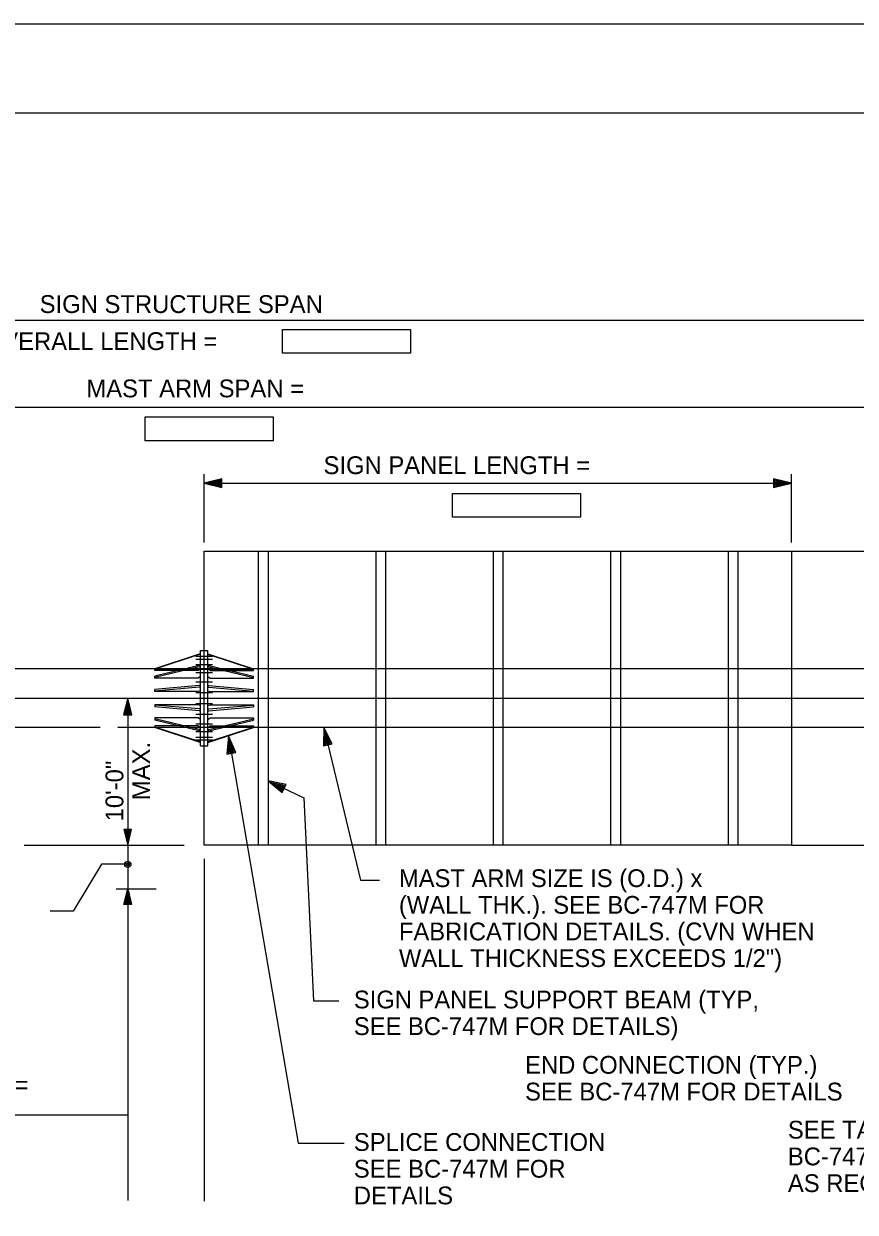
# Model space of a CAD drawing. Extents: x 640117 to 642655, y 297247 to 298435.
# Drawn here: x 641443.9 to 641584, y 298235.3 to 298435.5 of the extents above; entities that cross this region are included whole.
import ezdxf

# ---------------------------------------------------------------- set-up
doc = ezdxf.new("R2010")
doc.units = 0
for name, color, linetype in [('10', 7, 'Continuous'), ('2', 7, 'Continuous'), ('48', 7, 'Continuous'), ('49', 7, 'Continuous'), ('50', 7, 'Continuous'), ('52', 7, 'Continuous'), ('53', 7, 'Continuous'), ('55', 7, 'Continuous'), ('PLT-BNDY', 7, 'Continuous')]:
    doc.layers.add(name, color=color, linetype=linetype)

msp = doc.modelspace()

# ---------------------------------------------------------------- linework, layer by layer
at = {"layer": '10'}
for p, q in [((641461.47, 298321.9), (641461.47, 298237.29)), ((641460.81, 298299.8), (641461.47, 298297.16)), ((641462.13, 298299.8), (641460.81, 298299.8)), ((641461.01, 298299.64), (641461.47, 298297.8)), ((641461.93, 298299.64), (641461.01, 298299.64)), ((641461.21, 298299.49), (641461.47, 298298.45)), ((641461.73, 298299.49), (641461.21, 298299.49)), ((641461.39, 298299.43), (641461.47, 298299.1)), ((641461.47, 298297.16), (641462.13, 298299.8)), ((641461.47, 298297.8), (641461.93, 298299.64)), ((641461.47, 298298.45), (641461.73, 298299.49)), ((641461.47, 298299.1), (641461.55, 298299.41)), ((641444.03, 298297.16), (641470.96, 298297.16)), ((641459.54, 298289.76), (641466.27, 298289.76)), ((641460.81, 298287.12), (641461.47, 298289.76)), ((641461.01, 298287.28), (641461.47, 298289.12)), ((641461.47, 298289.76), (641462.13, 298287.12)), ((641461.47, 298289.12), (641461.93, 298287.28)), ((641462.13, 298287.12), (641460.81, 298287.12)), ((641461.93, 298287.28), (641461.01, 298287.28)), ((641461.21, 298287.43), (641461.47, 298288.47)), ((641461.73, 298287.43), (641461.21, 298287.43)), ((641461.39, 298287.49), (641461.47, 298287.83)), ((641461.47, 298288.47), (641461.73, 298287.43)), ((641461.47, 298287.83), (641461.55, 298287.51)), ((641461.47, 298251.67), (641424.27, 298251.67))]:
    msp.add_line(p, q, dxfattribs=at)
at = {"layer": '2'}
msp.add_line((640998.46, 298420.46), (641784.46, 298420.46), dxfattribs=at)
for points in [[(641487.54, 298383.98), (641509.09, 298383.98), (641509.09, 298379.98), (641487.54, 298379.98)], [(641464.43, 298369.25), (641485.97, 298369.25), (641485.97, 298365.25), (641464.43, 298365.25)], [(641516.19, 298356.38), (641537.74, 298356.38), (641537.74, 298352.38), (641516.19, 298352.38)]]:
    msp.add_lwpolyline(points, close=True, dxfattribs=at)
at = {"layer": '48'}
for p, q in [((641472.96, 298328.95), (641475.73, 298328.95)), ((641472.96, 298328.47), (641475.73, 298328.47)), ((641472.96, 298327.54), (641475.73, 298327.54)), ((641472.96, 298326.23), (641475.73, 298326.23)), ((641472.96, 298324.62), (641475.73, 298324.62)), ((641472.96, 298322.83), (641475.73, 298322.83)), ((641472.96, 298320.97), (641475.73, 298320.97)), ((641472.96, 298319.18), (641475.73, 298319.18)), ((641472.96, 298317.57), (641475.73, 298317.57)), ((641472.96, 298316.25), (641475.73, 298316.25)), ((641472.96, 298315.33), (641475.73, 298315.33)), ((641472.96, 298314.85), (641475.73, 298314.85))]:
    msp.add_line(p, q, dxfattribs=at)
at = {"layer": '49'}
for p, q in [((641474.34, 298346.63), (641573.28, 298346.63)), ((641474.34, 298297.16), (641474.34, 298346.63)), ((641483.47, 298346.63), (641483.47, 298297.16)), ((641485.11, 298346.63), (641485.11, 298297.16)), ((641503.25, 298346.63), (641503.25, 298297.16)), ((641504.9, 298346.63), (641504.9, 298297.16)), ((641523.04, 298346.63), (641523.04, 298297.16)), ((641524.69, 298346.63), (641524.69, 298297.16)), ((641542.83, 298346.63), (641542.83, 298297.16)), ((641544.48, 298346.63), (641544.48, 298297.16)), ((641562.62, 298346.63), (641562.62, 298297.16)), ((641564.27, 298346.63), (641564.27, 298297.16)), ((641573.28, 298346.63), (641573.28, 298297.16)), ((641573.28, 298346.63), (641637.17, 298346.63)), ((641573.28, 298297.16), (641474.34, 298297.16)), ((641573.28, 298297.16), (641637.17, 298297.16))]:
    msp.add_line(p, q, dxfattribs=at)
at = {"layer": '50'}
msp.add_line((641032.47, 298321.9), (641730.35, 298321.9), dxfattribs=at)
at = {"layer": '52'}
for p, q in [((641286.35, 298385.52), (641662.33, 298385.52)), ((641474.34, 298348.13), (641474.34, 298359.59)), ((641477.34, 298358.84), (641474.34, 298358.09)), ((641477.34, 298357.34), (641477.34, 298358.84)), ((641573.28, 298358.09), (641570.28, 298358.84)), ((641570.28, 298358.84), (641570.28, 298357.34)), ((641573.28, 298348.13), (641573.28, 298359.59)), ((641474.34, 298358.09), (641573.28, 298358.09)), ((641474.34, 298358.09), (641477.34, 298357.34)), ((641477.16, 298358.61), (641475.07, 298358.09)), ((641475.07, 298358.09), (641477.16, 298357.57)), ((641476.99, 298358.39), (641475.81, 298358.09)), ((641475.81, 298358.09), (641476.99, 298357.8)), ((641476.92, 298358.18), (641476.54, 298358.09)), ((641476.54, 298358.09), (641476.9, 298358)), ((641476.99, 298357.8), (641476.99, 298358.39)), ((641477.16, 298357.57), (641477.16, 298358.61)), ((641570.28, 298357.34), (641573.28, 298358.09)), ((641572.55, 298358.09), (641570.46, 298358.61)), ((641570.46, 298358.61), (641570.46, 298357.57)), ((641570.46, 298357.57), (641572.55, 298358.09)), ((641571.82, 298358.09), (641570.64, 298358.39)), ((641570.64, 298358.39), (641570.64, 298357.8)), ((641570.64, 298357.8), (641571.82, 298358.09)), ((641570.71, 298358), (641571.08, 298358.09)), ((641571.08, 298358.09), (641570.73, 298358.18)), ((641461.47, 298321.9), (641460.77, 298319.08)), ((641461.47, 298321.21), (641460.98, 298319.25)), ((641462.18, 298319.08), (641461.47, 298321.9)), ((641461.96, 298319.25), (641461.47, 298321.21)), ((641460.77, 298319.08), (641462.18, 298319.08)), ((641460.98, 298319.25), (641461.96, 298319.25)), ((641461.47, 298320.52), (641461.2, 298319.42)), ((641461.2, 298319.42), (641461.75, 298319.42)), ((641461.47, 298319.84), (641461.39, 298319.5)), ((641461.75, 298319.42), (641461.47, 298320.52)), ((641461.56, 298319.48), (641461.47, 298319.84)), ((641494.48, 298316.95), (641494.45, 298313.86)), ((641495.91, 298314.21), (641494.48, 298316.95)), ((641478.42, 298315.56), (641478.19, 298312.48)), ((641478.54, 298314.84), (641478.38, 298312.69)), ((641479.66, 298312.73), (641478.42, 298315.56)), ((641479.41, 298312.87), (641478.54, 298314.84)), ((641494.65, 298316.24), (641494.63, 298314.08)), ((641495.65, 298314.33), (641494.65, 298316.24)), ((641494.82, 298315.52), (641494.81, 298314.31)), ((641495.39, 298314.45), (641494.82, 298315.52)), ((641494.99, 298314.81), (641494.99, 298314.44)), ((641495.17, 298314.47), (641494.99, 298314.81)), ((641478.19, 298312.48), (641479.66, 298312.73)), ((641478.38, 298312.69), (641479.41, 298312.87)), ((641478.67, 298314.12), (641478.57, 298312.91)), ((641478.57, 298312.91), (641479.16, 298313.01)), ((641479.16, 298313.01), (641478.67, 298314.12)), ((641478.79, 298313.4), (641478.76, 298313.03)), ((641478.94, 298313.04), (641478.79, 298313.4)), ((641494.45, 298313.86), (641495.91, 298314.21)), ((641494.63, 298314.08), (641495.65, 298314.33)), ((641494.81, 298314.31), (641495.39, 298314.45)), ((641485.11, 298307.95), (641487.51, 298305.99)), ((641488.15, 298307.34), (641485.11, 298307.95)), ((641485.78, 298307.63), (641487.44, 298306.27)), ((641487.89, 298307.21), (641485.78, 298307.63)), ((641487.63, 298307.08), (641486.44, 298307.32)), ((641486.44, 298307.32), (641487.38, 298306.55)), ((641487.1, 298307.01), (641487.39, 298306.77)), ((641487.48, 298306.93), (641487.1, 298307.01)), ((641487.38, 298306.55), (641487.63, 298307.08)), ((641487.44, 298306.27), (641487.89, 298307.21)), ((641487.51, 298305.99), (641488.15, 298307.34)), ((641474.34, 298294.83), (641474.34, 298237.21))]:
    msp.add_line(p, q, dxfattribs=at)
for points in [[(641286.35, 298370.91), (641676.82, 298370.91)], [(641494.48, 298316.95), (641500.66, 298291.26), (641503.87, 298291.26)], [(641478.42, 298315.56), (641490.17, 298246.95), (641497.93, 298246.95)], [(641485.11, 298307.95), (641491.16, 298305.09), (641492.78, 298270.93), (641497.02, 298270.93)], [(641461.47, 298293.91), (641457.05, 298293.91), (641452.26, 298286.02), (641448.38, 298286.02)]]:
    msp.add_lwpolyline(points, dxfattribs=at)
for radius in [0.536, 0.268]:
    msp.add_circle((641461.47, 298293.91), radius, dxfattribs=at)
at = {"layer": '55'}
for p, q in [((641473.53, 298329.3), (641466.01, 298326.84)), ((641473.53, 298329.22), (641466.01, 298326.76)), ((641473.73, 298329.3), (641473.53, 298329.3)), ((641473.73, 298329.22), (641473.53, 298329.22)), ((641473.73, 298329.92), (641474.34, 298329.92)), ((641473.73, 298313.87), (641473.73, 298329.92)), ((641474.34, 298313.87), (641474.34, 298329.92)), ((641474.34, 298329.92), (641474.95, 298329.92)), ((641474.95, 298313.87), (641474.95, 298329.92)), ((641474.95, 298329.3), (641475.15, 298329.3)), ((641474.95, 298329.22), (641475.15, 298329.22)), ((641475.15, 298329.3), (641482.67, 298326.84)), ((641475.15, 298329.22), (641482.67, 298326.76)), ((641474.34, 298326.84), (641340.77, 298326.84)), ((641473.53, 298327.39), (641466.01, 298325.59)), ((641473.53, 298327.18), (641466.01, 298325.38)), ((641466.01, 298326.57), (641466.01, 298326.84)), ((641466.01, 298326.77), (641482.67, 298326.77)), ((641473.73, 298326.96), (641473.32, 298326.57)), ((641473.73, 298327.39), (641473.53, 298327.39)), ((641473.73, 298327.18), (641473.53, 298327.18)), ((641573.28, 298326.84), (641474.34, 298326.84)), ((641474.95, 298327.39), (641475.15, 298327.39)), ((641474.95, 298327.18), (641475.15, 298327.18)), ((641474.95, 298326.96), (641475.36, 298326.57)), ((641475.15, 298327.39), (641482.67, 298325.59)), ((641475.15, 298327.18), (641482.67, 298325.38)), ((641482.67, 298326.57), (641482.67, 298326.84)), ((641607.91, 298326.84), (641573.28, 298326.84)), ((641470.08, 298326.57), (641466.01, 298326.57)), ((641466.01, 298325.24), (641466.01, 298325.59)), ((641473.32, 298325.24), (641466.01, 298325.24)), ((641473.32, 298326.57), (641470.08, 298326.57)), ((641473.73, 298325.52), (641473.32, 298325.24)), ((641474.95, 298325.52), (641475.36, 298325.24)), ((641475.36, 298326.57), (641478.6, 298326.57)), ((641475.36, 298325.24), (641482.67, 298325.24)), ((641478.6, 298326.57), (641482.67, 298326.57)), ((641482.67, 298325.24), (641482.67, 298325.59)), ((641473.53, 298324.02), (641466.01, 298323.36)), ((641473.53, 298323.72), (641466.01, 298323.06)), ((641466.01, 298323.01), (641466.01, 298323.36)), ((641473.32, 298323.01), (641466.01, 298323.01)), ((641473.73, 298323.12), (641473.32, 298323.01)), ((641473.73, 298324.02), (641473.53, 298324.02)), ((641473.73, 298323.72), (641473.53, 298323.72)), ((641474.95, 298324.02), (641475.15, 298324.02)), ((641474.95, 298323.72), (641475.15, 298323.72)), ((641474.95, 298323.12), (641475.36, 298323.01)), ((641475.15, 298324.02), (641482.67, 298323.36)), ((641475.15, 298323.72), (641482.67, 298323.06)), ((641475.36, 298323.01), (641482.67, 298323.01)), ((641482.67, 298323.01), (641482.67, 298323.36)), ((641466.01, 298320.78), (641466.01, 298320.44)), ((641473.32, 298320.78), (641466.01, 298320.78)), ((641473.53, 298320.07), (641466.01, 298320.73)), ((641473.73, 298320.68), (641473.32, 298320.78)), ((641474.95, 298320.68), (641475.36, 298320.78)), ((641475.15, 298320.07), (641482.67, 298320.73)), ((641475.36, 298320.78), (641482.67, 298320.78)), ((641482.67, 298320.78), (641482.67, 298320.44)), ((641473.53, 298319.78), (641466.01, 298320.44)), ((641473.73, 298320.07), (641473.53, 298320.07)), ((641473.73, 298319.78), (641473.53, 298319.78)), ((641474.95, 298320.07), (641475.15, 298320.07)), ((641474.95, 298319.78), (641475.15, 298319.78)), ((641475.15, 298319.78), (641482.67, 298320.44)), ((641456.82, 298316.95), (641340.77, 298316.95)), ((641474.34, 298316.95), (641459.79, 298316.95)), ((641466.01, 298318.56), (641466.01, 298318.2)), ((641473.32, 298318.56), (641466.01, 298318.56)), ((641473.53, 298316.62), (641466.01, 298318.41)), ((641473.53, 298316.4), (641466.01, 298318.2)), ((641466.01, 298317.23), (641466.01, 298316.95)), ((641470.08, 298317.23), (641466.01, 298317.23)), ((641473.53, 298314.58), (641466.01, 298317.03)), ((641466.01, 298317.02), (641482.67, 298317.02)), ((641473.53, 298314.5), (641466.01, 298316.95)), ((641473.32, 298317.23), (641470.08, 298317.23)), ((641473.73, 298318.27), (641473.32, 298318.56)), ((641473.73, 298316.84), (641473.32, 298317.23)), ((641573.28, 298316.95), (641474.34, 298316.95)), ((641474.95, 298318.27), (641475.36, 298318.56)), ((641474.95, 298316.84), (641475.36, 298317.23)), ((641475.15, 298316.62), (641482.67, 298318.41)), ((641475.15, 298316.4), (641482.67, 298318.2)), ((641475.15, 298314.58), (641482.67, 298317.03)), ((641475.15, 298314.5), (641482.67, 298316.95)), ((641475.36, 298318.56), (641482.67, 298318.56)), ((641475.36, 298317.23), (641478.6, 298317.23)), ((641478.6, 298317.23), (641482.67, 298317.23)), ((641482.67, 298318.56), (641482.67, 298318.2)), ((641482.67, 298317.23), (641482.67, 298316.95)), ((641607.91, 298316.95), (641573.28, 298316.95)), ((641473.73, 298316.62), (641473.53, 298316.62)), ((641473.73, 298316.4), (641473.53, 298316.4)), ((641474.95, 298316.62), (641475.15, 298316.62)), ((641474.95, 298316.4), (641475.15, 298316.4)), ((641473.73, 298314.58), (641473.53, 298314.58)), ((641473.73, 298314.5), (641473.53, 298314.5)), ((641473.73, 298313.87), (641474.34, 298313.87)), ((641474.34, 298313.87), (641474.95, 298313.87)), ((641474.95, 298314.58), (641475.15, 298314.58)), ((641474.95, 298314.5), (641475.15, 298314.5))]:
    msp.add_line(p, q, dxfattribs=at)
at = {"layer": 'PLT-BNDY'}
msp.add_lwpolyline([(640958.46, 298435.46), (641799.46, 298435.46), (641799.46, 297841.46), (640958.46, 297841.46)], close=True, dxfattribs=at)

# ---------------------------------------------------------------- texts
at = {"layer": '10'}
for s, p in [('MAST ARM SIZE IS (O.D.) x', (641507.16, 298290.08)), ('(WALL THK.). SEE BC-747M FOR', (641507.16, 298285.59)), ('FABRICATION DETAILS. (CVN WHEN', (641507.16, 298281.11)), ('WALL THICKNESS EXCEEDS 1/2")', (641507.16, 298276.62)), ('SIGN PANEL SUPPORT BEAM (TYP,', (641499.57, 298269.65)), ('SEE BC-747M FOR DETAILS)', (641499.57, 298265.16))]:
    msp.add_text(s, height=2.9917, dxfattribs=at).set_placement(p)
at = {"layer": '2'}
for s, p in [('MAX.', (641465.23, 298304.72)), ('10\'-0"', (641460.73, 298301.14))]:
    msp.add_text(s, height=3, rotation=90, dxfattribs=at).set_placement(p)
for s, p in [('END CONNECTION (TYP.)', (641528.41, 298258.64)), ('ACTUAL VERT. CLR.=', (641403.42, 298255.31)), ('SEE BC-747M FOR DETAILS', (641528.41, 298254.14)), ('SEE TABLE "A", ON', (641572.69, 298247.72)), ('SPLICE CONNECTION', (641499.56, 298245.65)), ('BC-747M, SHT.5 OR', (641572.69, 298243.22)), ('SEE BC-747M FOR', (641499.56, 298241.15)), ("AS REQ'D. BY OWNER", (641572.69, 298238.72)), ('DETAILS', (641499.56, 298236.65))]:
    msp.add_text(s, height=3, dxfattribs=at).set_placement(p)
at = {"layer": '52'}
msp.add_text('OVERALL LENGTH =', height=3, dxfattribs=at).set_placement((641437.21, 298380.51))
at = {"layer": '53'}
for s, p in [('SIGN STRUCTURE SPAN', (641446.63, 298386.75)), ('MAST ARM SPAN =', (641454.5, 298372.55)), ('SIGN PANEL LENGTH =', (641494.46, 298359.62))]:
    msp.add_text(s, height=3, dxfattribs=at).set_placement(p)

doc.saveas('drawing.dxf')
